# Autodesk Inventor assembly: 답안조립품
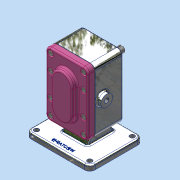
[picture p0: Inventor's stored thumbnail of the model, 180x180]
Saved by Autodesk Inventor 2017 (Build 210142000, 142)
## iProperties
Part Number: 답안조립품
Material: 일반
Document SubType Name: Assembly
Designer: MRC
Author: MRC
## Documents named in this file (11)
- C:\Users\MRC\Desktop\700407V1060\답안조립품.iam
- C:\Users\MRC\Desktop\700407V1060\본체.ipt
- C:\Users\MRC\Desktop\700407V1060\Ű 6 x 6 x 18.ipt
- C:\Users\MRC\Desktop\700407V1060\개스킷.ipt
- C:\Users\MRC\Desktop\700407V1060\메인축.ipt
- C:\Users\MRC\Desktop\700407V1060\베어링부시.ipt
- C:\Users\MRC\Desktop\700407V1060\볼트 M5.ipt
- C:\Users\MRC\Desktop\700407V1060\서브축.ipt
- C:\Users\MRC\Desktop\700407V1060\스퍼기어.ipt
- C:\Users\MRC\Desktop\700407V1060\오일 실 16 28 7.ipt
- C:\Users\MRC\Desktop\700407V1060\커버.ipt
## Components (3 placed, 2 different names)
1. Ű 6 x 6 x 18:1
2. 개스킷:1
3. Ű 6 x 6 x 18:2
